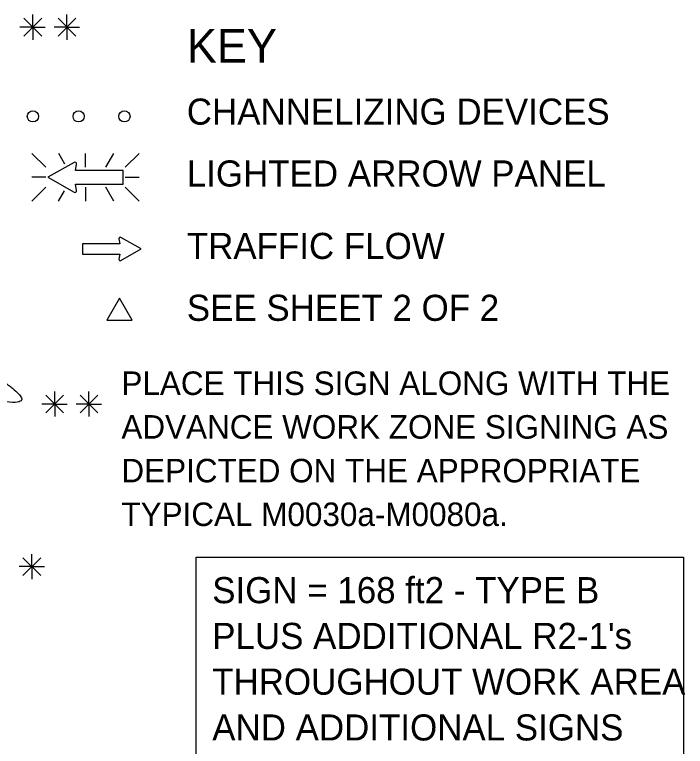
# Model space of a CAD drawing. Extents: x 16562 to 18475, y 6979 to 8243.
# Drawn here: x 17173.5 to 17412.5, y 7862.9 to 8123.6 of the extents above; entities that cross this region are included whole.
import ezdxf

# ---------------------------------------------------------------- set-up
doc = ezdxf.new("R2010")
doc.units = 0
for name, color, linetype in [('MT_SCRATCH_LEVEL_E', 7, 'Continuous'), ('TRAFFIC_SIGNS_PR', 7, 'Continuous'), ('TYPICAL_TEXT_DIMEN_EX', 7, 'Continuous'), ('TYPICAL_TEXT_DIMEN_PR', 7, 'Continuous')]:
    doc.layers.add(name, color=color, linetype=linetype)

msp = doc.modelspace()

# ---------------------------------------------------------------- linework, layer by layer
at = {"layer": 'MT_SCRATCH_LEVEL_E'}
for p, q in [((17210.67, 8043.76), (17210.99, 8041.98)), ((17210.67, 8043.76), (17210.99, 8041.98)), ((17218.6, 8040.13), (17211.36, 8044.24)), ((17218.6, 8040.13), (17211.36, 8044.24)), ((17210.99, 8041.98), (17197.73, 8041.98)), ((17197.73, 8041.98), (17197.73, 8038.24)), ((17210.99, 8041.98), (17197.73, 8041.98)), ((17197.73, 8041.98), (17197.73, 8038.24)), ((17211.36, 8035.99), (17218.6, 8040.13)), ((17211.36, 8035.99), (17218.6, 8040.13)), ((17197.73, 8038.24), (17210.99, 8038.24)), ((17197.73, 8038.24), (17210.99, 8038.24)), ((17210.99, 8038.24), (17210.67, 8036.46)), ((17210.99, 8038.24), (17210.67, 8036.46))]:
    msp.add_line(p, q, dxfattribs=at)
for centre, start, end in [((17211.13, 8043.83), 60.4248, 189.9638), ((17211.13, 8043.83), 60.4248, 189.9638), ((17211.13, 8036.39), 170.0362, 299.7731), ((17211.13, 8036.39), 170.0362, 299.7731)]:
    msp.add_arc(centre, 0.463, start, end, dxfattribs=at)
at = {"layer": 'TRAFFIC_SIGNS_PR'}
for p, q in [((17179.66, 8074.14), (17184.6, 8069.21)), ((17191.43, 8070.32), (17189.22, 8074.14)), ((17198.75, 8069.21), (17198.75, 8074.14)), ((17205.98, 8069.21), (17208.83, 8074.14)), ((17212.9, 8069.21), (17217.83, 8074.14)), ((17184.6, 8065.65), (17179.66, 8065.65)), ((17212.9, 8065.65), (17217.83, 8065.65)), ((17179.66, 8057.16), (17184.6, 8062.1)), ((17189.17, 8057.16), (17191.29, 8060.82)), ((17198.75, 8062.1), (17198.75, 8057.16)), ((17208.88, 8057.16), (17206.03, 8062.1)), ((17212.9, 8062.1), (17217.83, 8057.16))]:
    msp.add_line(p, q, dxfattribs=at)
for points in [[(17194.67, 8070.93), (17185.38, 8065.65), (17194.68, 8060.33)], [(17195.55, 8060.96), (17195.15, 8063.23), (17212.16, 8063.23), (17212.16, 8068.03), (17195.15, 8068.03), (17195.55, 8070.31)]]:
    msp.add_lwpolyline(points, dxfattribs=at)
for centre in [(17180.01, 8087.34), (17196.31, 8087.34), (17212.61, 8087.34)]:
    msp.add_circle(centre, 2, dxfattribs=at)
for centre, radius, start, end in [((17194.96, 8070.4), 0.598, 350.7308, 118.8916), ((17194.96, 8060.85), 0.597, 241.4833, 9.9593)]:
    msp.add_arc(centre, radius, start, end, dxfattribs=at)
at = {"layer": 'TYPICAL_TEXT_DIMEN_EX'}
msp.add_lwpolyline([(17238.13, 7930.32), (17411.78, 7930.32), (17411.78, 7839.99), (17238.13, 7839.99)], close=True, dxfattribs=at)
at = {"layer": 'TYPICAL_TEXT_DIMEN_PR'}
for p, q in [((17179.95, 8119.13), (17179.95, 8123.58)), ((17192.16, 8119.13), (17192.16, 8123.58)), ((17176.77, 8122.31), (17183.14, 8115.94)), ((17183.14, 8122.31), (17176.77, 8115.94)), ((17188.97, 8122.31), (17195.35, 8115.94)), ((17195.35, 8122.31), (17188.97, 8115.94)), ((17179.95, 8119.13), (17175.42, 8119.13)), ((17179.95, 8119.13), (17183.14, 8119.13)), ((17179.95, 8119.13), (17184.43, 8119.13)), ((17179.95, 8119.13), (17179.95, 8114.63)), ((17192.16, 8119.13), (17187.63, 8119.13)), ((17192.16, 8119.13), (17195.35, 8119.13)), ((17192.16, 8119.13), (17196.64, 8119.13)), ((17192.16, 8119.13), (17192.16, 8114.63)), ((17184.59, 7988.05), (17190.97, 7981.68)), ((17190.97, 7988.05), (17184.59, 7981.68)), ((17187.78, 7984.86), (17187.78, 7989.32)), ((17196.8, 7988.05), (17203.17, 7981.68)), ((17203.17, 7988.05), (17196.8, 7981.68)), ((17199.99, 7984.86), (17199.99, 7989.32)), ((17187.78, 7984.86), (17183.25, 7984.86)), ((17187.78, 7984.86), (17190.97, 7984.86)), ((17187.78, 7984.86), (17192.26, 7984.86)), ((17187.78, 7984.86), (17187.78, 7980.36)), ((17199.99, 7984.86), (17195.45, 7984.86)), ((17199.99, 7984.86), (17203.17, 7984.86)), ((17199.99, 7984.86), (17204.46, 7984.86)), ((17199.99, 7984.86), (17199.99, 7980.36)), ((17176.45, 7930.11), (17182.83, 7923.73)), ((17182.83, 7930.11), (17176.45, 7923.73)), ((17179.64, 7926.92), (17179.64, 7931.38)), ((17179.64, 7926.92), (17175.11, 7926.92)), ((17179.64, 7926.92), (17182.83, 7926.92)), ((17179.64, 7926.92), (17184.12, 7926.92)), ((17179.64, 7926.92), (17179.64, 7922.42))]:
    msp.add_line(p, q, dxfattribs=at)
msp.add_lwpolyline([(17210.88, 8022.62), (17206.35, 8014.79), (17215.4, 8014.79)], close=True, dxfattribs=at)
msp.add_open_spline([(17145.17, 8007.33), (17200.89, 7976.81), (17111.07, 8000.8), (17134.81, 7949.53)], degree=2, dxfattribs=at)

# ---------------------------------------------------------------- texts
at = {"layer": 'TRAFFIC_SIGNS_PR'}
for s, p in [('PLACE THIS SIGN ALONG WITH THE', (17211.55, 7988.08)), ('ADVANCE WORK ZONE SIGNING AS', (17211.55, 7972.52)), ('DEPICTED ON THE APPROPRIATE', (17211.55, 7956.95)), ('TYPICAL M0030a-M0080a.', (17211.55, 7941.39))]:
    msp.add_text(s, height=8.379, dxfattribs=at).set_placement(p)
at = {"layer": 'TYPICAL_TEXT_DIMEN_EX'}
for s, height, p in [('KEY', 12, (17234.85, 8106.44)), ('CHANNELIZING DEVICES', 9.3, (17234.85, 8084.39)), ('LIGHTED ARROW PANEL', 9.3, (17234.85, 8062.34)), ('TRAFFIC FLOW', 9.3, (17234.85, 8036.54)), ('SEE SHEET 2 OF 2', 9.3, (17234.85, 8014.49)), ('SIGN = 168 ft2 - TYPE B', 9.3, (17243.9, 7913.9)), ("PLUS ADDITIONAL R2-1's", 9.3, (17243.9, 7897.6)), ('THROUGHOUT WORK AREA', 9.3, (17243.9, 7881.3)), ('AND ADDITIONAL SIGNS', 9.3, (17243.9, 7864.99))]:
    msp.add_text(s, height=height, dxfattribs=at).set_placement(p)

doc.saveas('drawing.dxf')
